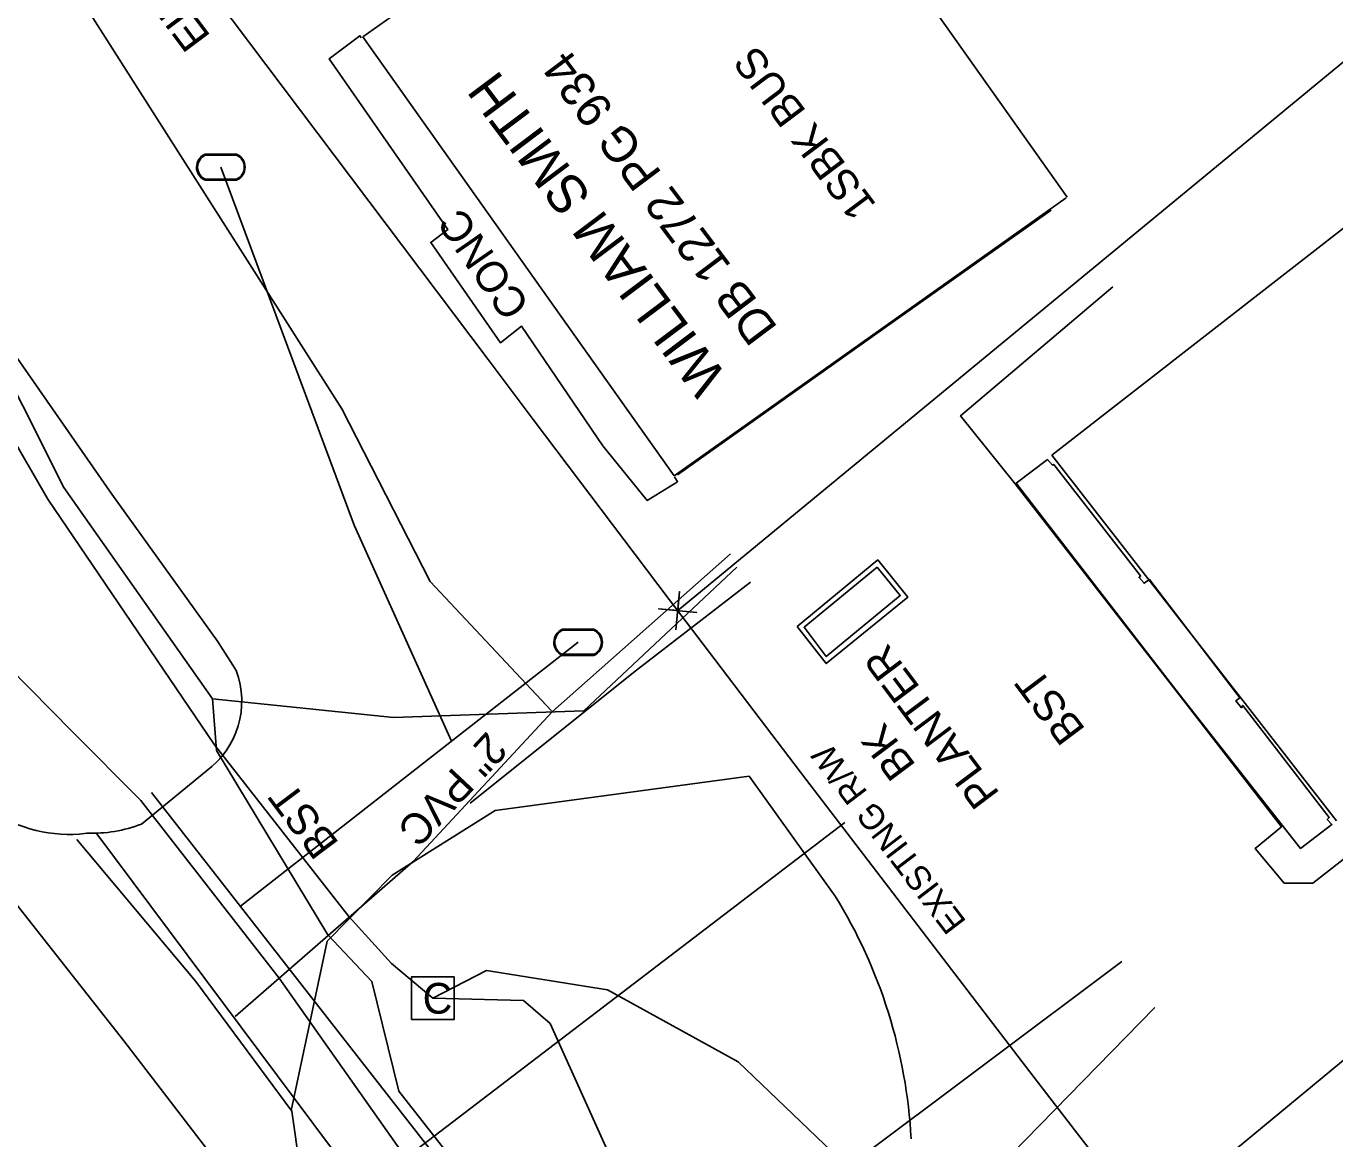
# Model space of a CAD drawing. Extents: x 1263837 to 1268319, y 770628 to 773628.
# Drawn here: x 1265984.3 to 1266154.5, y 773140.3 to 773284.9 of the extents above; entities that cross this region are included whole.
import ezdxf

# ---------------------------------------------------------------- set-up
doc = ezdxf.new("R2010")
doc.units = 0
for name, color, linetype in [('Exist Building', 7, 'Continuous'), ('Exist Building Text', 7, 'Continuous'), ('Exist Property Deed Book Text', 7, 'Continuous'), ('Exist Property Iron Pin Text', 7, 'Continuous'), ('Exist Roads EOP Other', 7, 'Continuous'), ('Exist Roads EOP Text', 7, 'Continuous'), ('Exist Roads EOT Text', 7, 'Continuous'), ('Exist Utilities Gas UG Line SUE LOS B', 7, 'Continuous'), ('Exist Utilities Gas UG Line SUE LOS B Text', 7, 'Continuous'), ('Exist Utilities Telephone UG Cable SUE LOS B', 7, 'Continuous'), ('Exist Utilities Telephone UG FO SUE LOS B', 7, 'Continuous'), ('Exist Utilities TV Pedestal CELL', 7, 'Continuous'), ('Exist Utilities TV UG Cable SUE LOS B', 7, 'Continuous'), ('Exist Utilities Water Meter CELL', 7, 'Continuous'), ('Exist Utilities Water UG Line SUE LOS B', 7, 'Continuous'), ('Prop Drainage Structure Pipe Alternate 42in Label', 7, 'Continuous'), ('Prop Drainage Structure Pipe RCP 60in Class III', 7, 'Continuous'), ('Prop Earthen Structure Base Ditch Special Cut with Rip Rap Detail CELL', 7, 'Continuous'), ('Prop Earthen Structure V Ditch Special Lateral with Rip Rap Detail CELL', 7, 'Continuous'), ('Prop Guardrail', 7, 'Continuous'), ('Prop Horizontal Alignment', 7, 'Continuous'), ('Prop SS Fill Text', 7, 'Continuous'), ('Prop SS Transition Line', 7, 'Continuous'), ('Scratch_Level_2', 7, 'Continuous')]:
    doc.layers.add(name, color=color, linetype=linetype)

# ---------------------------------------------------------------- blocks, each defined once
blk = doc.blocks.new('EXIST UTILITIES TV PEDESTAL')
at = {"layer": 'Exist Utilities TV Pedestal CELL'}
blk.add_line((0, 0), (0, 0), dxfattribs=at)
blk.add_lwpolyline([(-0.0555, -0.0555), (0.0555, -0.0555), (0.0555, 0.0555), (-0.0555, 0.0555), (-0.0555, -0.0555)], dxfattribs=at)
blk.add_text('C', height=0.08, dxfattribs=at).set_placement((-0.0261, -0.04))
blk = doc.blocks.new('EXIST UTILITIES WATER METER')
at = {"layer": 'Exist Utilities Water Meter CELL'}
blk.add_line((0, 0), (0, 0), dxfattribs=at)
for points in [[(-0.0408, 0.034), (0.0408, 0.034)], [(-0.0408, 0.0312), (0.0408, 0.0312)], [(0.0408, -0.0312), (-0.0413, -0.0312)], [(0.0408, -0.034), (-0.0413, -0.034)]]:
    blk.add_lwpolyline(points, dxfattribs=at)
for centre, radius, start, end in [((-0.0261, -0.0001), 0.0371, 113.178, 245.9794), ((-0.0259, -0.0001), 0.0347, 115.3009, 243.7824), ((0.0259, 0), 0.0371, 293.6483, 66.3084), ((0.0261, 0), 0.0345, 295.1272, 64.8728)]:
    blk.add_arc(centre, radius, start, end, dxfattribs=at)

msp = doc.modelspace()

# ---------------------------------------------------------------- linework, layer by layer
at = {"layer": 'Exist Building'}
for p, q in [((1266028.11, 773283.49), (1266079.22, 773319.73)), ((1266079.22, 773319.73), (1266119.68, 773262.67)), ((1266117.71, 773229.13), (1266217.56, 773306.87)), ((1266068.57, 773226.43), (1266028.11, 773283.49)), ((1266119.58, 773262.59), (1266068.57, 773226.43)), ((1266154.71, 773181.62), (1266117.71, 773229.13))]:
    msp.add_line(p, q, dxfattribs=at)
msp.add_lwpolyline([(1266094.99, 773214.59), (1266085.48, 773206.76), (1266088.36, 773202.96), (1266097.98, 773210.89), (1266094.99, 773214.59)], dxfattribs=at)
at = {"layer": 'Exist Roads EOP Other'}
msp.add_lwpolyline([(1266117.13, 773228.58), (1266113.04, 773225.48), (1266134.25, 773198.08), (1266150.04, 773178.02), (1266154.11, 773181.12), (1266153.51, 773181.76), (1266153.77, 773182.05), (1266142.53, 773196.6), (1266142.35, 773196.31), (1266141.62, 773197.19), (1266142.16, 773197.6), (1266130.38, 773212.98), (1266129.7, 773212.49), (1266129.04, 773213.21), (1266129.22, 773213.45), (1266117.94, 773227.92), (1266117.8, 773227.85), (1266117.13, 773228.58)], dxfattribs=at)
at = {"layer": 'Exist Utilities Gas UG Line SUE LOS B'}
for points in [[(1266036.84, 773212.69), (1266025.39, 773235.17), (1265945.24, 773360.91), (1265907.63, 773411.2), (1265870.37, 773457.5), (1265841.16, 773496.46), (1265798.38, 773548.13), (1265766.61, 773587.57), (1265741.28, 773620.95)], [(1266011.51, 773156.18), (1266034.63, 773176.31), (1266052.78, 773195.82), (1266075.91, 773216.3)], [(1266052.64, 773195.88), (1266036.84, 773212.69)], [(1266042.05, 773183.91), (1266063.67, 773201.2), (1266078.53, 773212.64)], [(1266301.62, 772793.02), (1266286.08, 772812.35), (1266262.09, 772842.01), (1266243.02, 772862.25), (1266220.48, 772886.92), (1266195.71, 772919.94), (1266176.51, 772945.32), (1266153.17, 772973.69), (1266133.95, 772998.15), (1266121.2, 773013.77), (1266092.73, 773049.43), (1266073.9, 773075.59), (1266049.68, 773105.06), (1266031.06, 773129.68), (1265993.52, 773179.92)]]:
    msp.add_lwpolyline(points, dxfattribs=at)
at = {"layer": 'Exist Utilities Telephone UG Cable SUE LOS B'}
for points in [[(1266008.56, 773197.45), (1265989.21, 773224.92), (1265973.15, 773256.87), (1265967.05, 773269.82), (1265965.99, 773276.3), (1265956.96, 773282.21), (1265914.32, 773338.24)], [(1266008.56, 773197.45), (1266032.09, 773195.03), (1266056.82, 773195.91), (1266076.75, 773214.57)], [(1266008.56, 773197.45), (1266009.09, 773190.74), (1266023.54, 773166.8), (1266029.29, 773160.74), (1266032.8, 773146.49), (1266050.24, 773124.2), (1266062.23, 773108.43), (1266069.25, 773105.19), (1266085.51, 773111.53), (1266106.83, 773132.5), (1266131.09, 773157.33)]]:
    msp.add_lwpolyline(points, dxfattribs=at)
at = {"layer": 'Exist Utilities Telephone UG FO SUE LOS B'}
for points in [[(1265999.24, 773184.25), (1265990.33, 773193.19), (1265970.8, 773212.97), (1265952.89, 773236.57), (1265916.43, 773280.82), (1265879.44, 773328.73), (1265847.68, 773371.25), (1265834.6, 773395.1), (1265824.26, 773419.4), (1265804.09, 773454.35), (1265785.8, 773488.81), (1265764.74, 773517.45), (1265749.42, 773546.59), (1265736.22, 773580.03), (1265719.88, 773610.09)], [(1266304.09, 772796.95), (1266282.68, 772823.11), (1266259.79, 772851.51), (1266238.02, 772877.36), (1266213.79, 772907.5), (1266201.34, 772925.88), (1266180.67, 772948.97), (1266158.66, 772974.99), (1266151.27, 772988.96), (1266128.09, 773021.69), (1266100.5, 773056.03), (1266080.08, 773080.34), (1266055.55, 773110.31), (1266036.49, 773133.81), (1266017.24, 773161.16), (1265999.24, 773184.25)]]:
    msp.add_lwpolyline(points, dxfattribs=at)
at = {"layer": 'Exist Utilities TV UG Cable SUE LOS B'}
for points in [[(1266008.79, 773191.47), (1265987.13, 773223.43), (1265969.64, 773253.65), (1265957.84, 773268.39), (1265923.64, 773320.24)], [(1266008.79, 773191.47), (1266026.29, 773169.17), (1266031.84, 773163.06), (1266037.19, 773158.54)], [(1266037.19, 773158.54), (1266044.2, 773162.17), (1266059.9, 773159.66), (1266076.9, 773150.3), (1266091.19, 773136.64), (1266126.79, 773163.31)], [(1266240.96, 772994.5), (1266228.99, 772979.18), (1266209.71, 772958.7), (1266202.18, 772964.91), (1266178.98, 772993.28), (1266169.92, 773001.47), (1266148.6, 773025.94), (1266136.73, 773039.4), (1266113.26, 773069.37), (1266114.17, 773073.73), (1266105.69, 773084.74), (1266081.06, 773110.3), (1266075.89, 773109.13), (1266068.28, 773120.21), (1266052.48, 773155.25), (1266049, 773158.25), (1266037.19, 773158.54)]]:
    msp.add_lwpolyline(points, dxfattribs=at)
at = {"layer": 'Exist Utilities Water Meter CELL'}
msp.add_line((1266009.64, 773266.56), (1266009.64, 773266.56), dxfattribs=at)
for points in [[(1266007.6, 773268.26), (1266011.68, 773268.26)], [(1266007.6, 773268.12), (1266011.68, 773268.12)], [(1266011.68, 773265), (1266007.58, 773265)], [(1266011.68, 773264.86), (1266007.58, 773264.86)]]:
    msp.add_lwpolyline(points, dxfattribs=at)
for centre, radius, start, end in [((1266008.33, 773266.55), 1.86, 113.178, 245.9794), ((1266008.35, 773266.55), 1.73, 115.3009, 243.7824), ((1266010.93, 773266.56), 1.86, 293.6483, 66.3084), ((1266010.95, 773266.56), 1.73, 295.1272, 64.8728)]:
    msp.add_arc(centre, radius, start, end, dxfattribs=at)
at = {"layer": 'Exist Utilities Water UG Line SUE LOS B'}
msp.add_line((1266012.18, 773170.51), (1266056.1, 773204.81), dxfattribs=at)
for points in [[(1266039.63, 773191.95), (1266026.96, 773220.03), (1266009.64, 773266.56)], [(1266307.35, 772809.88), (1266279.02, 772843.7), (1266261.57, 772864.93), (1266241.57, 772883.66), (1266222.07, 772905.04), (1266204.04, 772927.05), (1266182.99, 772951.84), (1266157.71, 772984.17), (1266000.63, 773185.3)]]:
    msp.add_lwpolyline(points, dxfattribs=at)
at = {"layer": 'Prop Drainage Structure Pipe Alternate 42in Label'}
msp.add_line((1266090.78, 773181.4), (1265987.11, 773102.29), dxfattribs=at)
at = {"layer": 'Prop Drainage Structure Pipe RCP 60in Class III'}
msp.add_line((1266069.05, 773208.92), (1266069.05, 773208.92), dxfattribs=at)
msp.add_lwpolyline([(1266068.81, 773206.43), (1266069.29, 773211.41), (1266069.05, 773208.92), (1266066.56, 773209.16), (1266071.54, 773208.68)], dxfattribs=at)
at = {"layer": 'Prop Guardrail'}
for p, q in [((1266069.05, 773208.92), (1266254.33, 773361.64)), ((1266130, 773129.33), (1266246.07, 773225.23))]:
    msp.add_line(p, q, dxfattribs=at)
at = {"layer": 'Prop Horizontal Alignment'}
msp.add_line((1266044.38, 773241.56), (1265753.15, 773628.27), dxfattribs=at)
msp.add_arc((1275094.23, 780056.99), 11329.16, 216.983333, 223.309327, dxfattribs=at)
at = {"layer": 'Prop SS Fill Text'}
for p, q in [((1266011.2, 773201.82), (1266011.64, 773201.15)), ((1266007.74, 773188.08), (1265999.31, 773181.18)), ((1265992.21, 773180), (1265991.27, 773179.87))]:
    msp.add_line(p, q, dxfattribs=at)
for points in [[(1266059.31, 773230.35), (1266048.74, 773245.88), (1266045.99, 773243.75), (1266036.93, 773256.77), (1266039.15, 773258.44), (1266023.73, 773280.64), (1266027.73, 773283.63), (1266027.88, 773283.39)], [(1266069.04, 773226.59), (1266097.06, 773246.45), (1266117.6, 773260.96)], [(1266125.63, 773251), (1266105.84, 773234.26), (1266112.93, 773225.42), (1266134.01, 773198.31), (1266147.56, 773180.84), (1266144.13, 773177.99), (1266147.91, 773173.52), (1266151.63, 773173.51), (1266156.97, 773177.68), (1266166.58, 773165.54), (1266185.99, 773180.34), (1266199.96, 773190.97)], [(1265976.81, 773250.8), (1265995.44, 773224.07), (1266009.21, 773204.95), (1266011.2, 773201.82)], [(1266059.31, 773230.35), (1266065.09, 773223.23), (1266069.02, 773225.68), (1266068.65, 773226.3)], [(1266084.56, 773206.86), (1266088.37, 773202.04), (1266098.97, 773210.67), (1266095.07, 773215.52), (1266084.56, 773206.86)], [(1266018.8, 773143.96), (1266023.47, 773165.97), (1266031.91, 773174.53), (1266045.3, 773182.97), (1266078.32, 773187.39), (1266089.53, 773171.81)], [(1265990.9, 773179.18), (1266006.38, 773160.72), (1266018.87, 773143.88), (1266020.92, 773129.52)]]:
    msp.add_lwpolyline(points, dxfattribs=at)
msp.add_arc((1265990.03, 773198.49), 18.66, 233.7193, 273.8245, dxfattribs=at)
for centre, major_axis, ratio, start_param, end_param in [((1266000.99, 773197.25), (-8.89, 7.13), 0.993313, 2.879647, 4.171109), ((1265992.77, 773197.45), (17.87, -1.03), 0.975379, 4.737325, 5.142357), ((1266032.57, 773136.72), (-44.11, 50.38), 0.999143, 4.046928, 4.545576)]:
    msp.add_ellipse(centre, major_axis=major_axis, ratio=ratio, start_param=start_param, end_param=end_param, dxfattribs=at)
at = {"layer": 'Prop SS Transition Line'}
msp.add_lwpolyline([(1265951.1, 773213.35), (1265978.42, 773176.6), (1265997.02, 773153.03), (1266022.4, 773120), (1266044.65, 773090.78), (1266069.51, 773058.32), (1266091.23, 773031.16), (1266119.47, 772995.3), (1266134.06, 772977.06), (1266160.18, 772943.7), (1266181.04, 772918.53), (1266210.29, 772881.31), (1266236.57, 772849.23), (1266263.03, 772815.74), (1266292.51, 772780.33), (1266321.33, 772744.69), (1266348.53, 772712.94), (1266379.06, 772676.58)], dxfattribs=at)
at = {"layer": 'Scratch_Level_2'}
msp.add_arc((1275094.23, 780056.99), 11459.16, 216.983333, 225.433333, dxfattribs=at)

# ---------------------------------------------------------------- block references
at = {"layer": 'Exist Utilities TV Pedestal CELL', "xscale": 50, "yscale": 50}
msp.add_blockref('EXIST UTILITIES TV PEDESTAL', (1266037.19, 773158.54), dxfattribs=at)
at = {"layer": 'Exist Utilities Water Meter CELL', "xscale": 50, "yscale": 50}
msp.add_blockref('EXIST UTILITIES WATER METER', (1266056.1, 773204.81), dxfattribs=at)

# ---------------------------------------------------------------- texts
at = {"layer": 'Exist Building Text'}
for s, p in [('1SBK BUS', (1266094.97, 773261.65)), ('PLANTER', (1266111.02, 773185.13)), ('BK ', (1266100.12, 773188.81))]:
    msp.add_text(s, height=4, rotation=126.9057, dxfattribs=at).set_placement(p)
at = {"layer": 'Exist Property Deed Book Text'}
msp.add_text('DB 1272 PG 934', height=4.5, rotation=126.9057, dxfattribs=at).set_placement((1266082.16, 773245.68))
at = {"layer": 'Exist Property Iron Pin Text'}
msp.add_text('EIP', height=4, rotation=126.9057, dxfattribs=at).set_placement((1266008.41, 773283.57))
at = {"layer": 'Exist Roads EOP Text'}
msp.add_text('CONC', height=4, rotation=124.8014, dxfattribs=at).set_placement((1266049.93, 773248.59))
at = {"layer": 'Exist Roads EOT Text'}
for p in [(1266122.17, 773193.46), (1266025.1, 773178.66)]:
    msp.add_text('BST', height=4, rotation=126.9057, dxfattribs=at).set_placement(p)
at = {"layer": 'Exist Utilities Gas UG Line SUE LOS B Text'}
msp.add_text('2" PVC', height=4, rotation=226.8634, dxfattribs=at).set_placement((1266044.27, 773193.37))
at = {"layer": 'Prop Earthen Structure Base Ditch Special Cut with Rip Rap Detail CELL'}
msp.add_text('WILLIAM SMITH', height=5, rotation=126.9057, dxfattribs=at).set_placement((1266075.61, 773239.29))
at = {"layer": 'Prop Earthen Structure V Ditch Special Lateral with Rip Rap Detail CELL'}
msp.add_text('EXISTING R/W', height=3.2, rotation=127.3658, dxfattribs=at).set_placement((1266106.68, 773168.49))

doc.saveas('drawing.dxf')
